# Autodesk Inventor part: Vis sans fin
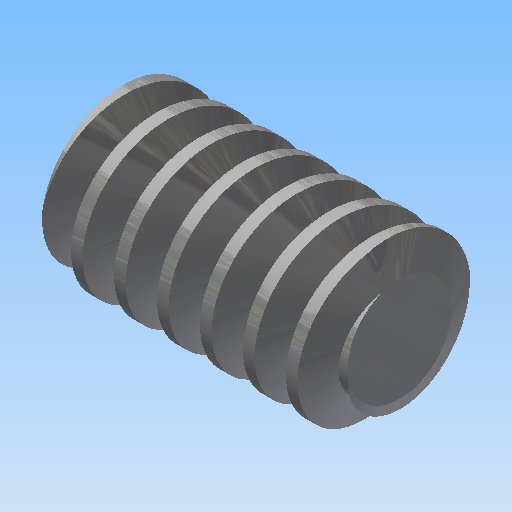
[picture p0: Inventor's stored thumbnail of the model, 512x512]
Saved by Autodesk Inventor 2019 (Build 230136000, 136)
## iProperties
Created: 2023-04
Part Number: Vis sans fin
Material: Steel, Mild
Document SubType Name: Modeling
Designer: Thier
Categories: <?xml version="1.0" encoding="UTF-16"?> <MemberInstance><Categories><FamilyTemplate><FamilyTemplateParameter ValueType="xs:double" Id="1" ObjectReferenceKey="da
Density: 7.86 g/cm^3
Appearance: Steel
CustomPartVersion: 1
Author: Thier
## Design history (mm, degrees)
body "Solid1"
extrude "Corps de base" new body stored distance "d6" = 42 (= da_b); taper "d7" = 0 deg
chamfer "Chamfer1" distance "d8" = 1.60147 (= fd_cham1); stored, may be unused: second distance "d9" = 4.4 (= 0.5 x fd_cham2), angle "d47" = 45 deg
chamfer "Chamfer2" distance "d10" = 1.60147 (= fd_cham1); stored, may be unused: second distance "d11" = 4.4 (= 0.5 x fd_cham2), angle "d48" = 45 deg
sketch "Esquisse de la dent"
  geometry: L1 (0, 21.74)-(0, 10.96) reference; L2 (-30.617, 12.12)-(-28.972, 7.6); L3 (-27.577, 7.6)-(-25.932, 12.12); L4 (-50.535, 0)-(-37.455, 0) reference; L5 (-30.617, 12.12)-(-28.274, 12.12); L6 (-28.274, 12.12)-(-25.932, 12.12); L7 (-28.972, 7.6)-(-28.274, 7.6); L8 (-28.274, 7.6)-(-27.577, 7.6); L9 (-28.274, 10)-(-26.704, 10); L10 (-28.274, 12.12)-(-28.274, 7.6)
  constraints: 16 end point, 3 equal length, 3 parallel, 2 collinear, 2 point on line
  dimensions: "d24" = 110 deg angle of L7 L2 (computed from da_alfat); "d25" = 28.27433 distance from line of L1 L5.end (= fd_dist); "d26" = 1.5708 distance of L9.start L9.end (= 0.25 x da_px); "d27" = 7.6 distance between parallel lines of L4 L7 (= 0.5 x da_df); "d28" = 10 distance between parallel lines of L4 L9 (= 0.5 x da_d); "d29" = 12.12 distance between parallel lines of L4 L5 (= 0.505 x da_da)
feature "Dent" pitch "d30" = 6.28319 (computed from da_px, da_z); turns "d32" = 9 (= fd_n); dims "d31" = 10, "d33" = 0, angle "d34" = 90 deg, angle "d35" = 90 deg, "d36" = 0, "d37" = 0, "d70" = 10, "da_rightdir" = 0 [user parameter]
pattern_circular "Motif de la dent" dims angle "d46" = 360 deg, "da_rightdir" = 0 [user parameter]
feature "Dent gauche" pitch "d62" = 6.28319 (computed from da_px, da_z); turns "d64" = 9 (= fd_n); dims "d63" = 10, "d65" = 0, angle "d66" = 90 deg, angle "d67" = 90 deg, "d68" = 0, "d69" = 0, "d76" = 10, "da_rightdir" = 0 [user parameter]
pattern_circular "Motif de dent gauche" dims angle "d73" = 360 deg, "da_rightdir" = 0 [user parameter]
node "Esquisse du corps de base" dims "d5" = 24 (= da_da)
sketch "Sketch5"
  geometry: C1 r 12 at (0, 0) reference; C2 r 10 at (0, 0)
  constraints: 1 centre point, 1 coincident
  dimensions: "d59" = 20 diameter of C2 (= da_d)
body "Srf1"
feature "Diamètre primitif" dims "d60" = 10, "d61" = 0
other parameters: "da_b" = 42 [user parameter; used in 3 equation terms], "da_df" = 15.2 [user parameter; used in 2 equation terms], "da_da" = 24 [user parameter; used in 3 equation terms], "fd_cham2" = 8.8 (= da_da - da_df) [user parameter; used in 3 equation terms], "fd_cham1" = 1.60147 (= 0.181985 x fd_cham2) [user parameter; used in 2 equation terms], "da_d" = 20 [user parameter; used in 2 equation terms], "da_px" = 36 deg [user parameter; used in 5 equation terms], "fd_dist" = 28.27433 (computed from da_b, da_px) [user parameter; used in 1 equation term], "fd_n" = 9 (computed from da_b, da_px) [user parameter; used in 2 equation terms], "da_alfat" = 20 deg [user parameter; used in 1 equation term], "d12" = 110 deg (derived), "d14" = 3.1425 (derived), "d50" = 0, "d54" = 0, "d56" = 0, "d77" = 0, "d80" = 0
